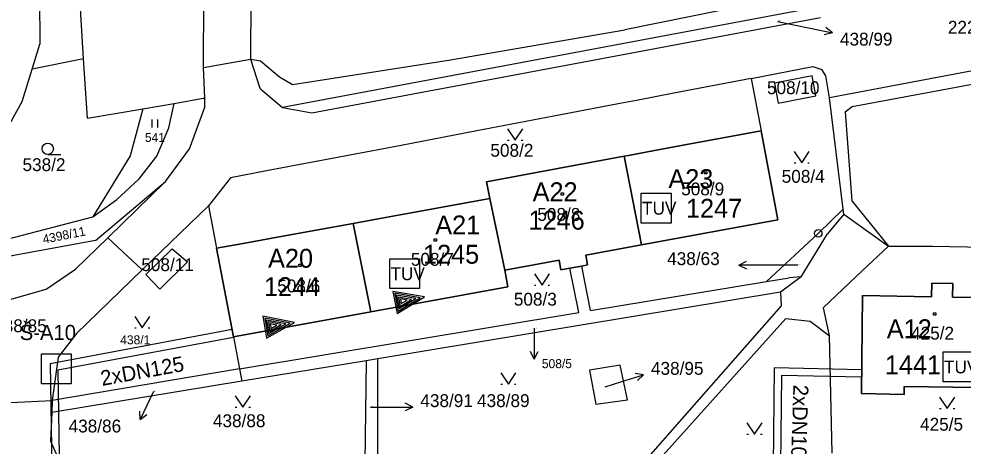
# Model space of a CAD drawing. Extents: x -468021 to -466942, y -1130484 to -1128584.
# Drawn here: x -467823.5 to -467698.5, y -1129026 to -1128969.4 of the extents above; entities that cross this region are included whole.
import ezdxf

# ---------------------------------------------------------------- set-up
doc = ezdxf.new("R2010")
doc.units = 0
for name, color, linetype in [('13-Redukce', 7, 'Continuous'), ('14a-Šachty', 7, 'Continuous'), ('18-TUV', 7, 'Continuous'), ('21-Označení-odběrného-místa', 7, 'Continuous'), ('22-Odběrná místa-šrafy', 7, 'Continuous'), ('25-Popisná-čísla', 7, 'Continuous'), ('Default', 7, 'Continuous'), ('DKM', 7, 'Continuous'), ('UT_SKUTEČNOST_staré', 7, 'Continuous')]:
    doc.layers.add(name, color=color, linetype=linetype)

# ---------------------------------------------------------------- blocks, each defined once
blk = doc.blocks.new('SACHTA')
at = {"layer": '14a-Šachty'}
blk.add_lwpolyline([(-0.0000139, 0.0000235), (0.0000256, 0.0000235), (0.0000256, -0.000016), (-0.0000139, -0.000016)], close=True, dxfattribs=at)
blk = doc.blocks.new('REDUKCE')
at = {"layer": '13-Redukce'}
for points in [[(-0.0132, 0.0075), (0.0266, 0.0221), (-0.0132, 0.0371), (-0.0132, 0.0075)], [(-0.0112, 0.0103), (0.0207, 0.0221), (-0.0112, 0.0343), (-0.0112, 0.0103)], [(-0.0092, 0.0131), (0.0149, 0.022), (-0.0092, 0.0313), (-0.0092, 0.0131)], [(-0.0073, 0.0158), (0.0089, 0.0221), (-0.0073, 0.0284), (-0.0073, 0.0158)], [(-0.0052, 0.0191), (0.0031, 0.0223), (-0.0052, 0.0256), (-0.0052, 0.0191)]]:
    blk.add_lwpolyline(points, dxfattribs=at)
blk = doc.blocks.new('TUV')
at = {"layer": '18-TUV'}
blk.add_lwpolyline([(-0.0000139, 0.0000235), (0.0000256, 0.0000235), (0.0000256, -0.000016), (-0.0000139, -0.000016)], close=True, dxfattribs=at)
blk.add_text('TUV', height=0.000017, dxfattribs=at).set_placement((-0.0000128, -0.0000048))

msp = doc.modelspace()

# ---------------------------------------------------------------- linework, layer by layer
at = {"layer": '22-Odběrná místa-šrafy'}
for points in [[(-467725.28, -1128984.23), (-467735.36, -1128986.1), (-467740.31, -1128987.02), (-467742.82, -1128987.48), (-467743.41, -1128987.59), (-467741.09, -1128999.34), (-467723.04, -1128996), (-467725.28, -1128984.23)], [(-467743.41, -1128987.59), (-467751.46, -1128989.09), (-467761.6, -1128990.97), (-467761.18, -1128993.18), (-467759.17, -1129002.69), (-467752.01, -1129001.36), (-467751.77, -1129002.64), (-467750.56, -1129002.42), (-467748.98, -1129002.13), (-467748.24, -1129001.99), (-467748.48, -1129000.71), (-467741.09, -1128999.34), (-467743.41, -1128987.59)], [(-467758.77, -1129004.9), (-467759.17, -1129002.69), (-467761.18, -1128993.18), (-467771.09, -1128994.99), (-467775.93, -1128995.87), (-467779.27, -1128996.48), (-467776.93, -1129008.2), (-467758.77, -1129004.9)], [(-467779.27, -1128996.48), (-467789.05, -1128998.27), (-467793.82, -1128999.14), (-467797.33, -1128999.78), (-467795.09, -1129011.49), (-467776.93, -1129008.2), (-467779.27, -1128996.48)], [(-467691.12, -1129006.38), (-467699.92, -1129006.24), (-467699.89, -1129004.44), (-467702.68, -1129004.39), (-467702.71, -1129006.2), (-467711.83, -1129006.03), (-467711.99, -1129019.01), (-467706.33, -1129019.12), (-467706.32, -1129018.05), (-467696.67, -1129018.2), (-467696.69, -1129019.28), (-467691.29, -1129019.36), (-467691.12, -1129006.38)]]:
    msp.add_lwpolyline(points, dxfattribs=at)
at = {"layer": 'DKM'}
for p, q in [((-467792.76, -1128930.76), (-467792.82, -1128974.76)), ((-467814.92, -1128974.72), (-467816.35, -1128952.33)), ((-467799.06, -1128975.85), (-467798.97, -1128956.05)), ((-467676.76, -1128957.39), (-467743.3, -1128970.85)), ((-467820.78, -1128959.46), (-467820.71, -1128972.77)), ((-467717.56, -1128967.81), (-467788.6, -1128981.15)), ((-467784.74, -1128981.86), (-467717.39, -1128969.25)), ((-467723.09, -1128969.77), (-467718.77, -1128970.65)), ((-467766.65, -1128974.89), (-467743.3, -1128970.85)), ((-467718.77, -1128970.65), (-467715.83, -1128971.25)), ((-467715.83, -1128971.25), (-467716.71, -1128970.56)), ((-467715.83, -1128971.25), (-467716.91, -1128971.54)), ((-467672.58, -1128971.67), (-467716.23, -1128979.85)), ((-467821.73, -1128976.08), (-467820.71, -1128972.77)), ((-467713.22, -1128981.03), (-467672.8, -1128973.52)), ((-467814.92, -1128974.72), (-467821.73, -1128976.08)), ((-467814.42, -1128982.58), (-467814.92, -1128974.72)), ((-467799.06, -1128975.85), (-467792.82, -1128974.76)), ((-467792.82, -1128974.76), (-467791.62, -1128978.6)), ((-467792.82, -1128974.76), (-467791.5, -1128974.95)), ((-467798.9, -1128979.9), (-467799.06, -1128975.85)), ((-467791.5, -1128974.95), (-467789.01, -1128977.08)), ((-467787.28, -1128978.1), (-467766.65, -1128974.89)), ((-467726.6, -1128977.33), (-467718.44, -1128975.74)), ((-467718.44, -1128975.74), (-467717.22, -1128976.12)), ((-467823.05, -1128980.35), (-467821.73, -1128976.08)), ((-467789.01, -1128977.08), (-467787.28, -1128978.1)), ((-467718.52, -1128976.96), (-467723.51, -1128977.91)), ((-467718.01, -1128979.61), (-467718.52, -1128976.96)), ((-467716.72, -1128976.96), (-467717.22, -1128976.12)), ((-467716.23, -1128979.85), (-467716.72, -1128976.96)), ((-467726.6, -1128977.33), (-467736.81, -1128979.27)), ((-467726.6, -1128977.33), (-467725.28, -1128984.23)), ((-467723.51, -1128977.91), (-467723.01, -1128980.56)), ((-467791.62, -1128978.6), (-467791.45, -1128978.74)), ((-467791.45, -1128978.74), (-467788.6, -1128981.15)), ((-467736.81, -1128979.27), (-467741.76, -1128980.22)), ((-467723.01, -1128980.56), (-467718.01, -1128979.61)), ((-467826.86, -1128987.21), (-467823.05, -1128980.35)), ((-467807.1, -1128981.31), (-467802.94, -1128980.6)), ((-467803.66, -1128983.83), (-467802.94, -1128980.6)), ((-467802.94, -1128980.6), (-467799.09, -1128979.93)), ((-467799.09, -1128979.93), (-467798.9, -1128979.9)), ((-467798.9, -1128981.1), (-467798.9, -1128979.9)), ((-467744.19, -1128980.68), (-467752.68, -1128982.3)), ((-467741.76, -1128980.22), (-467744.19, -1128980.68)), ((-467714.41, -1128994.61), (-467716.23, -1128979.85)), ((-467714.13, -1128981.73), (-467713.22, -1128981.03)), ((-467814.42, -1128982.58), (-467807.1, -1128981.31)), ((-467807.1, -1128981.31), (-467808.76, -1128987.53)), ((-467800.92, -1128986.61), (-467798.9, -1128981.1)), ((-467788.6, -1128981.15), (-467784.74, -1128981.86)), ((-467752.68, -1128982.3), (-467762.88, -1128984.24)), ((-467714.13, -1128981.73), (-467713.26, -1128993.5)), ((-467805.84, -1128983.79), (-467805.84, -1128982.74)), ((-467805.14, -1128982.74), (-467805.14, -1128983.79)), ((-467805.22, -1128987.57), (-467803.66, -1128983.83)), ((-467762.88, -1128984.24), (-467772.92, -1128986.16)), ((-467758.81, -1128983.96), (-467757.81, -1128985.46)), ((-467757.81, -1128985.46), (-467756.81, -1128983.96)), ((-467735.36, -1128986.1), (-467725.28, -1128984.23)), ((-467725.28, -1128984.23), (-467723.04, -1128996)), ((-467758.81, -1128985.46), (-467758.61, -1128985.46)), ((-467757.01, -1128985.46), (-467756.81, -1128985.46)), ((-467804.09, -1128990.95), (-467800.92, -1128986.61)), ((-467777.57, -1128987.04), (-467790.7, -1128989.55)), ((-467772.92, -1128986.16), (-467777.57, -1128987.04)), ((-467742.82, -1128987.48), (-467740.31, -1128987.02)), ((-467740.31, -1128987.02), (-467735.36, -1128986.1)), ((-467720.89, -1128986.96), (-467719.89, -1128988.46)), ((-467719.89, -1128988.46), (-467718.89, -1128986.96)), ((-467819.67, -1128987.36), (-467817.92, -1128987.36)), ((-467808.76, -1128987.53), (-467813.71, -1128995.62)), ((-467807.56, -1128990.57), (-467805.22, -1128987.57)), ((-467751.46, -1128989.09), (-467743.41, -1128987.59)), ((-467743.41, -1128987.59), (-467742.82, -1128987.48)), ((-467743.41, -1128987.59), (-467741.09, -1128999.34)), ((-467720.89, -1128988.46), (-467720.69, -1128988.46)), ((-467719.09, -1128988.46), (-467718.89, -1128988.46)), ((-467790.7, -1128989.55), (-467795.47, -1128990.45)), ((-467761.6, -1128990.97), (-467751.46, -1128989.09)), ((-467732.75, -1128989.64), (-467732.45, -1128989.64)), ((-467732.75, -1128989.94), (-467732.75, -1128989.64)), ((-467732.45, -1128989.64), (-467732.45, -1128989.94)), ((-467813.34, -1128998.77), (-467804.09, -1128990.95)), ((-467811.71, -1128998.38), (-467804.09, -1128990.95)), ((-467810.51, -1128993.34), (-467807.56, -1128990.57)), ((-467795.47, -1128990.45), (-467798.39, -1128994.18)), ((-467761.18, -1128993.18), (-467761.6, -1128990.97)), ((-467732.45, -1128989.94), (-467732.75, -1128989.94)), ((-467813.71, -1128995.62), (-467810.51, -1128993.34)), ((-467771.09, -1128994.99), (-467761.18, -1128993.18)), ((-467759.17, -1129002.69), (-467761.18, -1128993.18)), ((-467751.71, -1128992.45), (-467751.41, -1128992.45)), ((-467751.71, -1128992.75), (-467751.71, -1128992.45)), ((-467751.41, -1128992.75), (-467751.71, -1128992.75)), ((-467751.41, -1128992.45), (-467751.41, -1128992.75)), ((-467713.26, -1128993.5), (-467708.4, -1128999.49)), ((-467798.39, -1128994.18), (-467807.18, -1129002.63)), ((-467798.39, -1128994.18), (-467797.33, -1128999.78)), ((-467717.71, -1128997.81), (-467714.41, -1128994.61)), ((-467714.33, -1128995.28), (-467714.41, -1128994.61)), ((-467825.23, -1128998.63), (-467813.71, -1128995.62)), ((-467779.27, -1128996.48), (-467775.93, -1128995.87)), ((-467775.93, -1128995.87), (-467771.09, -1128994.99)), ((-467723.04, -1128996), (-467741.09, -1128999.34)), ((-467714.33, -1128995.28), (-467716.5, -1128997.86)), ((-467714.33, -1128995.28), (-467708.4, -1128999.49)), ((-467789.05, -1128998.27), (-467779.27, -1128996.48)), ((-467779.27, -1128996.48), (-467776.93, -1129008.2)), ((-467816.02, -1129002.56), (-467811.71, -1128998.38)), ((-467811.71, -1128998.38), (-467807.18, -1129002.63)), ((-467793.82, -1128999.14), (-467789.05, -1128998.27)), ((-467768.52, -1128998.52), (-467768.22, -1128998.52)), ((-467768.52, -1128998.82), (-467768.52, -1128998.52)), ((-467768.22, -1128998.52), (-467768.22, -1128998.82)), ((-467724.54, -1129004.17), (-467717.71, -1128997.81)), ((-467719.97, -1129003.55), (-467716.5, -1128997.86)), ((-467813.34, -1128998.77), (-467829.64, -1129001.75)), ((-467797.33, -1128999.78), (-467793.82, -1128999.14)), ((-467795.09, -1129011.49), (-467797.33, -1128999.78)), ((-467768.22, -1128998.82), (-467768.52, -1128998.82)), ((-467741.09, -1128999.34), (-467748.48, -1129000.71)), ((-467711.88, -1129002.76), (-467708.4, -1128999.49)), ((-467708.4, -1128999.49), (-467702.6, -1128999.5)), ((-467702.6, -1128999.5), (-467682.18, -1128999.86)), ((-467806.69, -1129003.25), (-467803.2, -1128999.87)), ((-467803.2, -1128999.87), (-467801.17, -1129001.57)), ((-467748.48, -1129000.71), (-467748.24, -1129001.99)), ((-467804.83, -1129005.17), (-467801.17, -1129001.57)), ((-467786.45, -1129001.89), (-467786.15, -1129001.89)), ((-467786.45, -1129002.19), (-467786.45, -1129001.89)), ((-467786.15, -1129002.19), (-467786.45, -1129002.19)), ((-467786.15, -1129001.89), (-467786.15, -1129002.19)), ((-467752.01, -1129001.36), (-467759.17, -1129002.69)), ((-467751.77, -1129002.64), (-467752.01, -1129001.36)), ((-467748.98, -1129002.13), (-467750.56, -1129002.42)), ((-467748.24, -1129001.99), (-467748.98, -1129002.13)), ((-467747.83, -1129008.03), (-467748.98, -1129002.13)), ((-467728.21, -1129002), (-467727.21, -1129001.5)), ((-467725.21, -1129002), (-467728.21, -1129002)), ((-467728.21, -1129002), (-467727.21, -1129002.5)), ((-467720.39, -1129002), (-467725.21, -1129002)), ((-467819.87, -1129005.17), (-467816.02, -1129002.56)), ((-467807.18, -1129002.63), (-467815.85, -1129011.07)), ((-467806.69, -1129003.25), (-467804.83, -1129005.17)), ((-467759.17, -1129002.69), (-467758.77, -1129004.9)), ((-467755.26, -1129003.14), (-467754.26, -1129004.64)), ((-467754.26, -1129004.64), (-467753.26, -1129003.14)), ((-467750.56, -1129002.42), (-467751.77, -1129002.64)), ((-467749.4, -1129008.29), (-467750.56, -1129002.42)), ((-467717.07, -1129007.65), (-467711.88, -1129002.76)), ((-467755.26, -1129004.64), (-467755.06, -1129004.64)), ((-467753.46, -1129004.64), (-467753.26, -1129004.64)), ((-467747.83, -1129008.03), (-467724.54, -1129004.17)), ((-467724.54, -1129004.17), (-467721.57, -1129003.68)), ((-467719.97, -1129003.55), (-467722.68, -1129005.57)), ((-467719.97, -1129003.55), (-467721.57, -1129003.68)), ((-467702.71, -1129006.2), (-467702.68, -1129004.39)), ((-467702.68, -1129004.39), (-467699.89, -1129004.44)), ((-467699.89, -1129004.44), (-467699.92, -1129006.24)), ((-467825.62, -1129006.81), (-467819.87, -1129005.17)), ((-467758.77, -1129004.9), (-467776.93, -1129008.2)), ((-467722.68, -1129005.57), (-467775.97, -1129014.4)), ((-467722.68, -1129005.57), (-467722.6, -1129007.4)), ((-467711.99, -1129019.01), (-467711.83, -1129006.03)), ((-467711.83, -1129006.03), (-467702.71, -1129006.2)), ((-467699.92, -1129006.24), (-467691.12, -1129006.38)), ((-467776.93, -1129008.2), (-467795.09, -1129011.49)), ((-467794.29, -1129015.73), (-467749.4, -1129008.29)), ((-467722.6, -1129007.4), (-467740.89, -1129028.19)), ((-467717.07, -1129007.65), (-467716.26, -1129011.33)), ((-467702.46, -1129008.32), (-467702.16, -1129008.32)), ((-467702.46, -1129008.62), (-467702.46, -1129008.32)), ((-467702.16, -1129008.32), (-467702.16, -1129008.62)), ((-467808.16, -1129008.79), (-467807.16, -1129010.29)), ((-467807.16, -1129010.29), (-467806.16, -1129008.79)), ((-467738.63, -1129027.61), (-467722.01, -1129009.06)), ((-467722.01, -1129009.06), (-467718.76, -1129009.42)), ((-467718.76, -1129009.42), (-467716.26, -1129011.33)), ((-467702.16, -1129008.62), (-467702.46, -1129008.62)), ((-467808.16, -1129010.29), (-467807.96, -1129010.29)), ((-467806.36, -1129010.29), (-467806.16, -1129010.29)), ((-467755.28, -1129010.37), (-467755.28, -1129011.45)), ((-467815.85, -1129011.07), (-467818.28, -1129014.18)), ((-467795.09, -1129011.49), (-467794.29, -1129015.73)), ((-467755.28, -1129011.45), (-467755.28, -1129014.45)), ((-467716.26, -1129011.33), (-467715.89, -1129026.89)), ((-467755.28, -1129014.45), (-467755.78, -1129013.45)), ((-467755.28, -1129014.45), (-467754.78, -1129013.45)), ((-467818.28, -1129014.18), (-467819.1, -1129019.94)), ((-467777.54, -1129014.66), (-467793.97, -1129017.37)), ((-467777.54, -1129014.78), (-467777.7, -1129028.1)), ((-467775.97, -1129014.4), (-467777.54, -1129014.66)), ((-467777.54, -1129014.78), (-467777.54, -1129014.66)), ((-467776, -1129028.11), (-467775.97, -1129014.56)), ((-467775.97, -1129014.56), (-467775.97, -1129014.4)), ((-467794.29, -1129015.73), (-467819.1, -1129019.94)), ((-467794.29, -1129015.73), (-467793.97, -1129017.37)), ((-467743.9, -1129015.25), (-467747.99, -1129015.93)), ((-467747.99, -1129015.93), (-467747.16, -1129020.41)), ((-467742.94, -1129019.82), (-467743.9, -1129015.25)), ((-467759.71, -1129016.24), (-467758.71, -1129017.74)), ((-467758.71, -1129017.74), (-467757.71, -1129016.24)), ((-467743.7, -1129017.41), (-467740.84, -1129016.52)), ((-467740.84, -1129016.52), (-467741.94, -1129016.34)), ((-467740.84, -1129016.52), (-467741.64, -1129017.29)), ((-467793.97, -1129017.37), (-467819.14, -1129021.52)), ((-467759.71, -1129017.74), (-467759.51, -1129017.74)), ((-467757.91, -1129017.74), (-467757.71, -1129017.74)), ((-467745.91, -1129018.1), (-467743.7, -1129017.41)), ((-467706.32, -1129018.05), (-467706.33, -1129019.12)), ((-467696.67, -1129018.2), (-467706.32, -1129018.05)), ((-467806.16, -1129019.75), (-467807.46, -1129022.45)), ((-467805.67, -1129018.73), (-467806.16, -1129019.75)), ((-467794.85, -1129019.29), (-467793.85, -1129020.79)), ((-467793.85, -1129020.79), (-467792.85, -1129019.29)), ((-467706.33, -1129019.12), (-467711.99, -1129019.01)), ((-467701.65, -1129019.5), (-467700.65, -1129021)), ((-467700.65, -1129021), (-467699.65, -1129019.5)), ((-467824.6, -1129020.19), (-467819.1, -1129019.94)), ((-467819.1, -1129019.94), (-467819.14, -1129021.52)), ((-467794.85, -1129020.79), (-467794.65, -1129020.79)), ((-467793.05, -1129020.79), (-467792.85, -1129020.79)), ((-467776.95, -1129020.79), (-467774.36, -1129020.79)), ((-467774.36, -1129020.79), (-467771.36, -1129020.79)), ((-467771.36, -1129020.79), (-467772.36, -1129020.29)), ((-467771.36, -1129020.79), (-467772.36, -1129021.29)), ((-467747.16, -1129020.41), (-467742.94, -1129019.82)), ((-467701.65, -1129021), (-467701.45, -1129021)), ((-467699.85, -1129021), (-467699.65, -1129021)), ((-467819.14, -1129021.52), (-467819.29, -1129025.31)), ((-467807.46, -1129022.45), (-467807.48, -1129021.33)), ((-467807.46, -1129022.45), (-467806.58, -1129021.77)), ((-467727.14, -1129022.86), (-467726.14, -1129024.36)), ((-467726.14, -1129024.36), (-467725.14, -1129022.86)), ((-467727.14, -1129024.36), (-467726.94, -1129024.36)), ((-467725.34, -1129024.36), (-467725.14, -1129024.36)), ((-467819.29, -1129025.31), (-467818.35, -1129027.45))]:
    msp.add_line(p, q, dxfattribs=at)
for centre, radius in [((-467819.67, -1128986.61), 0.75), ((-467717.71, -1128997.81), 0.5), ((-467717.71, -1128997.81), 0.01)]:
    msp.add_circle(centre, radius, dxfattribs=at)
at = {"layer": 'UT_SKUTEČNOST_staré'}
for points in [[(-467795.28, -1129010.52), (-467819.33, -1129015.08), (-467818.2, -1129086.87)], [(-467795.07, -1129011.58), (-467818.32, -1129015.9), (-467817.22, -1129086.89)], [(-467711.95, -1129015.86), (-467723.55, -1129015.58), (-467723.78, -1129037.21)], [(-467711.96, -1129016.84), (-467722.56, -1129016.61), (-467722.77, -1129036.21)]]:
    msp.add_lwpolyline(points, dxfattribs=at)

# ---------------------------------------------------------------- block references
at = {"layer": '13-Redukce'}
for p, xscale, yscale, rotation in [((-467772.01, -1129008.88), 100, 100.00000000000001, 10.8903147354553), ((-467789.29, -1129012.21), 100.00000000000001, 100, 9.464536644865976)]:
    msp.add_blockref('REDUKCE', p, dxfattribs=dict(at, xscale=xscale, yscale=yscale, rotation=rotation))
at = {"layer": '14a-Šachty', "xscale": 100000, "yscale": 100000}
msp.add_blockref('SACHTA', (-467819.13, -1129016.11), dxfattribs=at)
at = {"layer": 'Default', "xscale": 100000, "yscale": 100000}
for p in [(-467739.74, -1128994.85), (-467773.03, -1129003.52), (-467699.78, -1129015.85)]:
    msp.add_blockref('TUV', p, dxfattribs=at)

# ---------------------------------------------------------------- texts
at = {"layer": '14a-Šachty'}
msp.add_text('Š-A10', height=2, dxfattribs=at).set_placement((-467823.37, -1129011.92))
at = {"layer": '21-Označení-odběrného-místa'}
for s, p in [('A23', (-467737.53, -1128991.81)), ('A22', (-467755.5, -1128993.55)), ('A21', (-467768.39, -1128997.94)), ('A20', (-467790.51, -1129002.35)), ('A12', (-467708.63, -1129011.68))]:
    msp.add_text(s, height=2.5, dxfattribs=at).set_placement(p)
at = {"layer": '25-Popisná-čísla'}
for s, p in [('1247', (-467735.21, -1128995.73)), ('1246', (-467756.05, -1128997.31)), ('1245', (-467770.01, -1129001.82)), ('1244', (-467791.06, -1129006.11)), ('1441', (-467708.89, -1129016.45))]:
    msp.add_text(s, height=2.5, dxfattribs=at).set_placement(p)
at = {"layer": 'DKM'}
for s, height, p in [('438/99', 0.1, (-467723.09, -1128969.77)), ('222/1', 1.7, (-467700.55, -1128971.38)), ('438/99', 1.7, (-467714.83, -1128972.95)), ('508/10', 1.7, (-467724.49, -1128979.38)), ('541', 1.19, (-467806.81, -1128985.7)), ('508/2', 1.7, (-467761.09, -1128987.66)), ('538/2', 1.7, (-467823.01, -1128989.56)), ('508/4', 1.7, (-467722.54, -1128991.11)), ('508/9', 1.7, (-467735.84, -1128992.77)), ('508/8', 1.7, (-467754.88, -1128996.15)), ('508/11', 1.7, (-467807.29, -1129002.8)), ('508/7', 1.7, (-467771.62, -1129002.09)), ('438/63', 1.7, (-467737.7, -1129002)), ('438/63', 0.1, (-467720.39, -1129002)), ('508/6', 1.7, (-467789.3, -1129005.61)), ('508/3', 1.7, (-467757.99, -1129007.37)), ('438/85', 1.7, (-467826.76, -1129010.88)), ('508/5', 0.1, (-467755.28, -1129010.37)), ('425/2', 1.7, (-467705.42, -1129011.86)), ('438/1', 1.19, (-467810.08, -1129012.49)), ('508/5', 1.19, (-467754.28, -1129015.64)), ('438/95', 1.7, (-467739.84, -1129016.52)), ('438/95', 0.1, (-467745.91, -1129018.1)), ('438/86', 0.1, (-467805.67, -1129018.73)), ('438/91', 1.7, (-467770.36, -1129020.79)), ('438/89', 1.7, (-467762.86, -1129020.79)), ('438/91', 0.1, (-467776.95, -1129020.79)), ('438/88', 1.7, (-467797.81, -1129023.45)), ('425/5', 1.7, (-467704.23, -1129023.92)), ('438/86', 1.7, (-467816.91, -1129024.15))]:
    msp.add_text(s, height=height, dxfattribs=at).set_placement(p)
msp.add_text('4398/11', height=1.19, rotation=11.3366, dxfattribs=at).set_placement((-467820.22, -1128999.19))
at = {"layer": 'UT_SKUTEČNOST_staré'}
for s, rotation, p in [('2xDN125', 10.3319, (-467812.48, -1129018)), ('2xDN100', 268.1868, (-467720.99, -1129017.81))]:
    msp.add_text(s, height=2, rotation=rotation, dxfattribs=at).set_placement(p)

doc.saveas('drawing.dxf')
